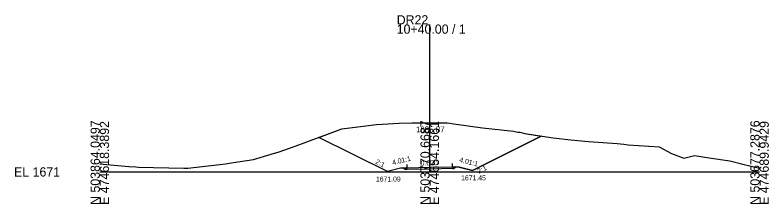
# Model space of a CAD drawing. Extents: x -26 to 1203, y -10 to 9633.
# Drawn here: x -25.7 to 202.8, y 990.3 to 1047.5 of the extents above; entities that cross this region are included whole.
import ezdxf

# ---------------------------------------------------------------- set-up
doc = ezdxf.new("R2010")
doc.units = 0
for name, color, linetype in [('Exist Cross Section Cell', 7, 'Continuous'), ('Exist XS Center Line Elevation Label', 7, 'Continuous'), ('Exist XS Ground Line', 7, 'Continuous'), ('Prop XS Ditch Slope Text', 7, 'Continuous'), ('Prop XS Ditch Standard Text', 7, 'Continuous'), ('Prop XS Earthwork Shape', 7, 'Continuous'), ('Prop XS EOT Tick Mark', 7, 'Continuous'), ('Prop XS Finish Grade', 7, 'Continuous'), ('Prop XS Finish Grade Earthwork', 7, 'Continuous'), ('Prop XS Finish Grade Pavement', 7, 'Continuous'), ('Prop XS Pvmt Edge Slope', 7, 'Continuous'), ('Prop XS SE Text', 7, 'Continuous'), ('Prop XS Shoulder Borrow Shape', 7, 'Continuous'), ('Prop XS Side Slope Text', 7, 'Continuous'), ('Prop XS Subgrade Earthwork', 7, 'Continuous'), ('Scratch_Level_5', 7, 'Continuous')]:
    doc.layers.add(name, color=color, linetype=linetype)

msp = doc.modelspace()

# ---------------------------------------------------------------- linework, layer by layer
at = {"layer": 'Exist Cross Section Cell'}
for p, q in [((100, 1000), (100, 1044.65)), ((0, 1000), (100, 1000)), ((100, 1000), (200, 1000))]:
    msp.add_line(p, q, dxfattribs=at)
at = {"layer": 'Exist XS Ground Line'}
msp.add_lwpolyline([(0, 1002.44), (1.03, 1002.38), (8.75, 1001.61), (10.94, 1001.49), (11.72, 1001.4), (25.5, 1001.14), (26.68, 1001.14), (36.42, 1002.23), (38.11, 1002.49), (40.49, 1002.86), (46.6, 1003.8), (51.96, 1005.37), (54.36, 1006.03), (59.23, 1007.77), (73.34, 1013.05), (83.89, 1014.36), (90.7, 1014.73), (94.61, 1014.82), (100, 1014.87), (100.89, 1014.88), (105.32, 1014.83), (108.06, 1014.47), (116.03, 1013.39), (125.43, 1012.3), (126.74, 1012.04), (127.32, 1012), (128.85, 1011.67), (137.45, 1010.28), (142.79, 1009.69), (148.16, 1009.25), (156.81, 1008.56), (158.87, 1008.38), (160.15, 1008.23), (169.58, 1007.56), (173.29, 1005.6), (177.06, 1004.18), (180.29, 1004.92), (184.76, 1004.31), (191, 1003.33), (194.88, 1002.36), (200, 1001.14)], dxfattribs=at)
at = {"layer": 'Prop XS Earthwork Shape'}
msp.add_lwpolyline([(106.92, 1000.99), (100, 1000.85), (93.19, 1000.71), (92.63, 1000.7), (92.16, 1001.17), (91.18, 1001.09), (87.18, 1000.09), (66.41, 1010.45), (73.34, 1013.05), (83.89, 1014.36), (90.7, 1014.73), (94.61, 1014.82), (100, 1014.87), (100.89, 1014.88), (105.32, 1014.83), (108.06, 1014.47), (116.03, 1013.39), (125.43, 1012.3), (126.74, 1012.04), (127.32, 1012), (128.85, 1011.67), (133.82, 1010.87), (112.94, 1000.45), (108.93, 1001.45), (107.95, 1001.49), (107.46, 1001)], close=True, dxfattribs=at)
at = {"layer": 'Prop XS EOT Tick Mark'}
for p, q in [((93.19, 1001.25), (93.19, 1002.25)), ((106.92, 1001.53), (106.92, 1002.53))]:
    msp.add_line(p, q, dxfattribs=at)
at = {"layer": 'Prop XS Finish Grade'}
for p, q in [((93.19, 1001.25), (92.16, 1001.17)), ((106.92, 1001.53), (107.95, 1001.49))]:
    msp.add_line(p, q, dxfattribs=at)
at = {"layer": 'Prop XS Finish Grade Earthwork'}
for p, q in [((87.18, 1000.09), (66.41, 1010.45)), ((112.94, 1000.45), (133.82, 1010.87)), ((91.18, 1001.09), (87.18, 1000.09)), ((92.16, 1001.17), (91.18, 1001.09)), ((107.95, 1001.49), (108.93, 1001.45)), ((108.93, 1001.45), (112.94, 1000.45))]:
    msp.add_line(p, q, dxfattribs=at)
at = {"layer": 'Prop XS Finish Grade Pavement'}
for p, q in [((93.19, 1001.25), (100, 1001.39)), ((100, 1001.39), (106.92, 1001.53))]:
    msp.add_line(p, q, dxfattribs=at)
at = {"layer": 'Prop XS Pvmt Edge Slope'}
for p, q in [((93.19, 1001.25), (92.63, 1000.7)), ((106.92, 1001.53), (107.46, 1001))]:
    msp.add_line(p, q, dxfattribs=at)
at = {"layer": 'Prop XS Shoulder Borrow Shape'}
for points in [[(93.19, 1001.25), (92.16, 1001.17), (92.63, 1000.7)], [(106.92, 1001.53), (107.95, 1001.49), (107.46, 1001)]]:
    msp.add_lwpolyline(points, close=True, dxfattribs=at)
at = {"layer": 'Prop XS Subgrade Earthwork'}
for p, q in [((92.63, 1000.7), (92.16, 1001.17)), ((106.92, 1000.99), (100, 1000.85)), ((106.92, 1000.99), (107.46, 1001)), ((107.46, 1001), (107.95, 1001.49)), ((93.19, 1000.71), (92.63, 1000.7)), ((100, 1000.85), (93.19, 1000.71))]:
    msp.add_line(p, q, dxfattribs=at)
at = {"layer": 'Scratch_Level_5'}
msp.add_lwpolyline([(0, 1002.44), (1.03, 1002.38), (8.75, 1001.61), (10.94, 1001.49), (11.72, 1001.4), (25.5, 1001.14), (26.68, 1001.14), (36.42, 1002.23), (38.11, 1002.49), (40.49, 1002.86), (46.6, 1003.8), (51.96, 1005.37), (54.36, 1006.03), (59.23, 1007.77), (73.34, 1013.05), (83.89, 1014.36), (90.7, 1014.73), (94.61, 1014.82), (100, 1014.87), (100.89, 1014.88), (105.32, 1014.83), (108.06, 1014.47), (116.03, 1013.39), (125.43, 1012.3), (126.74, 1012.04), (127.32, 1012), (128.85, 1011.67), (137.45, 1010.28), (142.79, 1009.69), (148.16, 1009.25), (156.81, 1008.56), (158.87, 1008.38), (160.15, 1008.23), (169.58, 1007.56), (173.29, 1005.6), (177.06, 1004.18), (180.29, 1004.92), (184.76, 1004.31), (191, 1003.33), (194.88, 1002.36), (200, 1001.14)], dxfattribs=at)

# ---------------------------------------------------------------- texts
at = {"layer": 'Exist Cross Section Cell'}
for s, p in [('DR22', (90, 1044.65)), ('10+40.00 / 1', (90, 1041.85)), ('EL 1671', (-26, 998.6))]:
    msp.add_text(s, height=2.8, dxfattribs=at).set_placement(p)
for s, p in [('N 503864.0497', (0, 990)), ('E 474618.3892', (2.8, 990)), ('N 503770.6687', (100, 990)), ('E 474654.1661', (102.8, 990)), ('N 503677.2876', (200, 990)), ('E 474689.9429', (202.8, 990))]:
    msp.add_text(s, height=2.8, rotation=90, dxfattribs=at).set_placement(p)
at = {"layer": 'Exist XS Center Line Elevation Label'}
msp.add_text('1685.87', height=1.8, dxfattribs=at).set_placement((95.83, 1011.95))
at = {"layer": 'Prop XS Ditch Slope Text'}
for rotation, p in [(14.0066, (88.82, 1002.05)), (345.988, (108.88, 1003.01))]:
    msp.add_text('4.01:1', height=1.5, rotation=rotation, dxfattribs=at).set_placement(p)
at = {"layer": 'Prop XS Ditch Standard Text'}
for s, p in [('1671.45', (109.54, 997.45)), ('1671.09', (83.71, 997.09))]:
    msp.add_text(s, height=1.5, dxfattribs=at).set_placement(p)
at = {"layer": 'Prop XS SE Text'}
msp.add_text('0.020', height=1.5, rotation=1.1458, dxfattribs=at).set_placement((97.28, 1001.93))
at = {"layer": 'Prop XS Side Slope Text'}
for rotation, p in [(333.4854, (83.39, 1002.6)), (26.5237, (114.9, 999.45))]:
    msp.add_text('2:1', height=1.5, rotation=rotation, dxfattribs=at).set_placement(p)

doc.saveas('drawing.dxf')
